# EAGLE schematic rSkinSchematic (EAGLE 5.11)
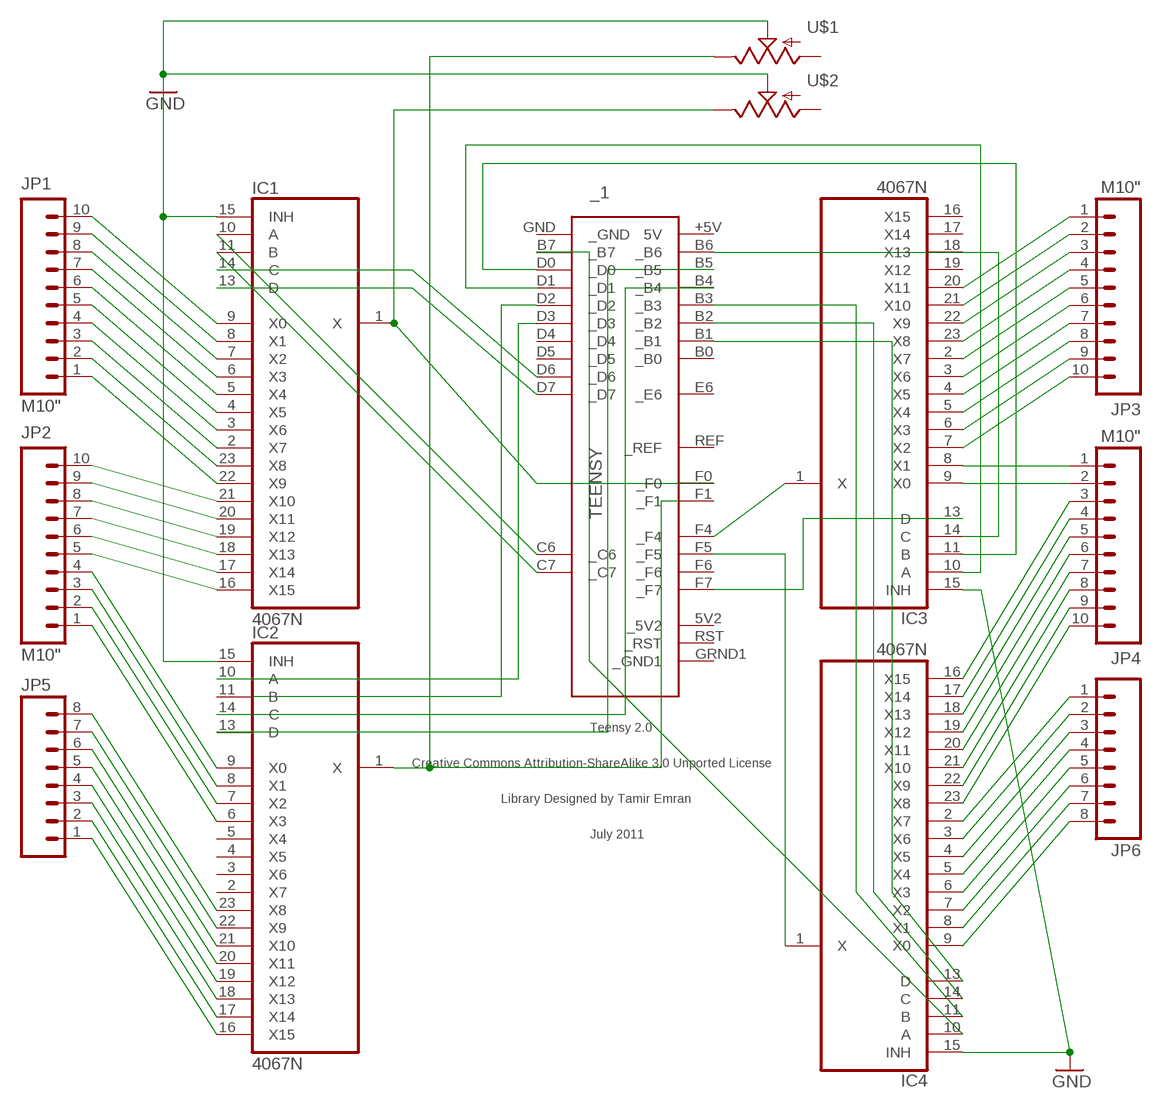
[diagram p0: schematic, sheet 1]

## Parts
_1  TEENSY  [TEENSY]
IC1  4067N  [DIL24-6]
IC2  4067N  [DIL24-6]
IC3  4067N  [DIL24-6]
IC4  4067N  [DIL24-6]
JP1  M10"  [1X10]
JP2  M10"  [1X10]
JP3  M10"  [1X10]
JP4  M10"  [1X10]
JP5  M08  [1X08]
JP6  M08  [1X08]
U$1  POT  [ALPS_POT]
U$2  POT  [ALPS_POT]

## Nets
GND: IC1.15(INH) IC2.15(INH) IC3.15(INH) IC4.15(INH) U$1.P$2(S) U$2.P$2(S)
N$1: _1.F0(_F0) IC1.1(X) U$2.P$1(E)
N$2: IC2.1(X) U$1.P$1(E)
N$3: _1.F4(_F4) IC3.1(X)
N$4: _1.F5(_F5) IC4.1(X)
N$5: _1.C6(_C6) IC1.10(A)
N$6: _1.C7(_C7) IC1.11(B)
N$7: _1.D6(_D6) IC1.14(C)
N$8: _1.D7(_D7) IC1.13(D)
N$9: _1.D2(_D2)
N$10: _1.D3(_D3) IC2.10(A)
N$11: _1.B4(_B4) IC2.14(C)
N$12: _1.B5(_B5) IC2.13(D)
N$13: _1.D1(_D1) IC3.10(A)
N$14: _1.D0(_D0) IC3.11(B)
N$15: _1.B7(_B7) IC4.10(A)
N$16: _1.B3(_B3) IC4.11(B)
N$17: _1.B6(_B6) IC3.14(C)
N$18: _1.F7(_F7) IC3.13(D)
N$19: _1.B2(_B2) IC4.14(C)
N$20: _1.B1(_B1) IC4.13(D)
N$21: IC1.9(X0) JP1.10
N$22: IC1.8(X1) JP1.9
N$23: IC1.7(X2) JP1.8
N$24: IC1.6(X3) JP1.7
N$25: IC1.5(X4) JP1.6
N$26: IC1.4(X5) JP1.5
N$27: IC1.3(X6) JP1.4
N$28: IC1.2(X7) JP1.3
N$29: IC1.23(X8) JP1.2
N$30: IC1.22(X9) JP1.1
N$31: IC1.21(X10) JP2.10
N$32: IC1.20(X11) JP2.9
N$33: IC1.19(X12) JP2.8
N$34: IC1.18(X13) JP2.7
N$35: IC1.17(X14) JP2.6
N$36: IC1.16(X15) JP2.5
N$37: IC2.9(X0) JP2.4
N$38: IC2.8(X1) JP2.3
N$39: IC2.7(X2) JP2.2
N$40: IC2.6(X3) JP2.1
N$41: IC2.23(X8) JP5.8
N$42: IC2.22(X9) JP5.7
N$43: IC2.21(X10) JP5.6
N$44: IC2.20(X11) JP5.5
N$45: IC2.19(X12) JP5.4
N$46: IC2.18(X13) JP5.3
N$47: IC2.17(X14) JP5.2
N$48: IC2.16(X15) JP5.1
N$49: IC3.20(X11) JP3.1
N$50: IC3.21(X10) JP3.2
N$51: IC3.22(X9) JP3.3
N$52: IC3.23(X8) JP3.4
N$53: IC3.2(X7) JP3.5
N$54: IC3.3(X6) JP3.6
N$55: IC3.4(X5) JP3.7
N$56: IC3.5(X4) JP3.8
N$57: IC3.6(X3) JP3.9
N$58: IC3.7(X2) JP3.10
N$59: IC3.8(X1) JP4.1
N$60: IC3.9(X0) JP4.2
N$61: IC4.16(X15) JP4.3
N$62: IC4.17(X14) JP4.4
N$63: IC4.18(X13) JP4.5
N$64: IC4.19(X12) JP4.6
N$65: IC4.20(X11) JP4.7
N$66: IC4.21(X10) JP4.8
N$67: IC4.22(X9) JP4.9
N$68: IC4.23(X8) JP4.10
N$69: IC4.2(X7) JP6.1
N$70: IC4.3(X6) JP6.2
N$71: IC4.4(X5) JP6.3
N$72: IC4.5(X4) JP6.4
N$73: IC4.6(X3) JP6.5
N$74: IC4.7(X2) JP6.6
N$75: IC4.8(X1) JP6.7
N$76: IC4.9(X0) JP6.8
Unconnected: _1.5V2(_5V2) _1.+5V(5V) _1.B0(_B0) _1.D4(_D4) _1.D5(_D5) _1.E6(_E6) _1.F1(_F1) _1.F6(_F6) _1.GND(_GND) _1.GRND1(_GND1) _1.REF(_REF) _1.RST(_RST) IC2.2(X7) IC2.3(X6) IC2.4(X5) IC2.5(X4) IC2.11(B) IC3.16(X15) IC3.17(X14) IC3.18(X13) IC3.19(X12) U$1.P$3(A) U$2.P$3(A)

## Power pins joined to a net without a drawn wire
VDD: IC1.24(VDD) IC2.24(VDD) IC3.24(VDD) IC4.24(VDD)
VSS: IC1.12(VSS) IC2.12(VSS) IC3.12(VSS) IC4.12(VSS)

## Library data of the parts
_1 = teensy:TEENSY: Teensy 2.0 Original Design by Clint Fisher Modified Design by Tamir Emran Licensed Under Creative Commons Attribution-ShareAlike 3.0 Unported (CC BY-SA 3.0)
IC1-IC4 = 40xx:4067: 16-channel ANALOG MULTIPLEXER
JP1-JP4 = SparkFun:M10: Header 10 Standard 10-pin 0.1" header. Use with straight break away headers (SKU : PRT-00116), right angle break away headers (PRT-00553), swiss pins (PRT-00743), machine pins (PRT-00117), and female headers (PRT-00115).
JP5 JP6 = SparkFun:M08: Header 8 Standard 8-pin 0.1" header. Use with straight break away headers (SKU : PRT-00116), right angle break away headers (PRT-00553), swiss pins (PRT-00743), machine pins (PRT-00117), and female headers (PRT-00115).
U$1 U$2 = SparkFun:POT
